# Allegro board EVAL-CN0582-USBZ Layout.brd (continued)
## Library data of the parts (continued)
J6 = CNBNC2P: User Part Number: UPN; Tolerance: N/A; alternate symbols: (); part number: CNBNC2P_TH-227161-1,E000900,CNAMP227161-1; tolerance: N/A
L1 = IND: User Part Number: UPN; Tolerance: 20; alternate symbols: (); part number: IND_SM-6.8UH,20,E017909,LSMSQ157H122; tolerance: 20
L2 L4 = IND: User Part Number: UPN; Tolerance: 20; alternate symbols: (); part number: IND_SM-4.7UH,20,E013623,LSMSQ157H122; tolerance: 20
L3 = IND: User Part Number: UPN; Tolerance: 20; alternate symbols: (); part number: IND_SM-8.2UH,20,E025126,LSMSQ157H161; tolerance: 20
M1 = MODUSB24P_4PSHLD: User Part Number: UPN; Tolerance: N/A; alternate symbols: (); part number: MODUSB24P_4PSHLD_SM-12401598E4#2A,E031205,M12401598E4_2A; tolerance: N/A
P1-P4 = CN2P: User Part Number: UPN; Tolerance: N/A; alternate symbols: (); part number: CN2P_TH-TSW-102-07-G-S,E031850,CNTHMHDR1X2L200W98H343; tolerance: N/A
P5 P14 = CN3P: User Part Number: UPN; Tolerance: N/A; alternate symbols: (); part number: CN3P_TH-1751251,E032001,CNPHOENIX1751251; tolerance: N/A
P7 = CN10P: User Part Number: UPN; Tolerance: N/A; alternate symbols: (); part number: CN10P_SM-TC2050-IDC,E021763,CNTC2050-IDC; tolerance: N/A
P8 = NC3P: Tolerance: N/A; User Part Number: UPN; alternate symbols: (); part number: NC3P_SM-TESTPAD3P,E020654,TP3SM29X147; tolerance: N/A
P9 P11 = CN10P: User Part Number: UPN; Tolerance: N/A; alternate symbols: (); part number: CN10P_TH-TSW-105-07-T-D,E054281,CNSAMTEC2X5H338LD36; tolerance: N/A
P10 = CN6P_ODD_EVEN: Tolerance: N/A; User Part Number: UPN; alternate symbols: (); part number: CN6P_ODD_EVEN_TH-TSW-103-08-T-D,E031364,CNSAMTEC2X3H330LD36; tolerance: N/A
P12 = CN2P: User Part Number: UPN; Tolerance: N/A; alternate symbols: (); part number: CN2P_TH-EDZ250/2,E013453,CNTH1X2H394; tolerance: N/A
Q1-Q4 Q9 Q10 = TRANNFET: User Part Number: UPN; Tolerance: N/A; alternate symbols: (); part number: TRANNFET_SM-DMN2005K-7,E011365,SOT23-2; tolerance: N/A
Q5-Q8 = TRANPMOSFET_V12: User Part Number: UPN; Tolerance: N/A; alternate symbols: (); part number: TRANPMOSFET_V12_SM-IRLML6401TRPBF,E023655,SOT23-M3; tolerance: N/A
R1 R6 R77 R79 R89 R98 R100 R101 R114 R149 R179 R184-R189 R191 R192 R196 R198-R200 R205-R207 R227 R229 R248 R257-R263 R287 R291 R292 R294 R296 R310 R313 R315-R317 R319 R320 R331 R332 R337 R338 R342 R352 R353 R355-R357 R368-R371 = RES: User Part Number: UPN; Tolerance: 1; alternate symbols: (R0402L,R0402L_ALT); part number: RES_SM-10K,E003751,1/10W,1,R0402; tolerance: 1
R2-R5 R111 R132 R139 R150 R154 R157 R181 R240-R244 R246 R277 R312 R314 R326 R327 R333 R349 R354 = RES: User Part Number: UPN; Tolerance: 1; alternate symbols: (R0402L,R0402L_ALT); part number: RES_SM-1K,E003763,1/10W,1,R0402; tolerance: 1
R7 R8 R13 R14 R23-R26 R47 R48 R57-R60 R78 R82-R88 R99 R102-R104 R109 R112 R113 R115-R117 R121 R128 R151 R153 R158 R180 R190 R195 R201-R204 R224 R225 R228 R230 R231 R234-R236 R239 R245 R247 R253 R255 R256 R264-R267 R274-R276 R278-R280 R283 R284 R293 R318 R323 R324 R330 R334 R335 R339 R340 R344 R350 R351 R358-R367 R372-R375 = RES: User Part Number: UPN; Tolerance: JUMPER; alternate symbols: (R0402L,R0402L_ALT); part number: RES_SM-0,E003438,1/10W,JUMPER,R0402; tolerance: JUMPER
R9 R10 R43 R44 R290 = RES: User Part Number: UPN; Tolerance: 1; alternate symbols: (R0402L); part number: RES_SM-120K,E015615,1/10W,1,R0402; tolerance: 1
R11 R12 R15 R16 R45 R46 R49 R50 R197 R208-R210 R297 R325 R328 R329 R347 = RES: User Part Number: UPN; Tolerance: 1; alternate symbols: (R0402L,R0402L_ALT); part number: RES_SM-100K,E003796,1/10W,1,R0402; tolerance: 1
R17 R18 R51 R52 = RES: User Part Number: UPN; Tolerance: 1; alternate symbols: (R0402L); part number: RES_SM-300,E049577,1/5W,1,R0402; tolerance: 1
R19 R20 R53 R54 R346 R348 = RES: User Part Number: UPN; Tolerance: 0.1; alternate symbols: (R0402L); part number: RES_SM-49.9K,E033966,1/16W,0.1,R0402; tolerance: 0.1
R21 R22 R55 R56 R108 = RES: User Part Number: UPN; Tolerance: 0.1; alternate symbols: (R0402L); part number: RES_SM-15K,E014275,1/16W,0.1,R0402; tolerance: 0.1
R27-R30 R61-R64 = RES: User Part Number: UPN; Tolerance: 0.1; alternate symbols: (R0402L); part number: RES_SM-750,E031657,1/16W,0.1,R0402; tolerance: 0.1
R31-R34 R65-R68 = RES: User Part Number: UPN; Tolerance: 0.1; alternate symbols: (R0402L); part number: RES_SM-374,E033965,1/10W,0.1,R0402; tolerance: 0.1
R35-R38 R69-R72 = RES: User Part Number: UPN; Tolerance: 0.1; alternate symbols: (R0402L); part number: RES_SM-2K,E031286,1/16W,0.1,R0402; tolerance: 0.1
R39-R42 R73-R76 = RES: User Part Number: UPN; Tolerance: 0.1; alternate symbols: (R0603L); part number: RES_SM-82.5,E018865,1/10W,0.1,R0603; tolerance: 0.1
R80 R106 = RES: User Part Number: UPN; Tolerance: 1; alternate symbols: (R0402L); part number: RES_SM-332K,E003766,1/10W,1,R0402; tolerance: 1
R81 = RES: User Part Number: UPN; Tolerance: 1; alternate symbols: (R0402L); part number: RES_SM-16K,E027681,1/10W,1,R0402; tolerance: 1
R90 = RES: User Part Number: UPN; Tolerance: 1; alternate symbols: (R0402L); part number: RES_SM-1MEG,E003749,1/10W,1,R0402; tolerance: 1
R91 = RES: User Part Number: UPN; Tolerance: 1; alternate symbols: (R0402L); part number: RES_SM-63.4K,E006803,1/10W,1,R0402; tolerance: 1
R92 = RES: User Part Number: UPN; Tolerance: 1; alternate symbols: (R0402L); part number: RES_SM-28K,E010020,1/10W,1,R0402; tolerance: 1
R93 = RES: User Part Number: UPN; Tolerance: 1; alternate symbols: (R0402L); part number: RES_SM-6.49K,E026140,1/10W,1,R0402; tolerance: 1
R94 = RES: User Part Number: UPN; Tolerance: 1; alternate symbols: (R0402L); part number: RES_SM-7.32K,E022433,1/10W,1,R0402; tolerance: 1
R95 = RES: User Part Number: UPN; Tolerance: 0.1; alternate symbols: (R0402L); part number: RES_SM-90.9K,E042560,1/16W,0.1,R0402; tolerance: 0.1
R96 = RES: User Part Number: UPN; Tolerance: 1; alternate symbols: (R0402L); part number: RES_SM-4.75K,E019642,1/16W,1,R0402; tolerance: 1
R97 = RES: User Part Number: UPN; Tolerance: 1; alternate symbols: (R0402L); part number: RES_SM-57.6K,E022063,1/16W,1,R0402; tolerance: 1
R105 = RES: User Part Number: UPN; Tolerance: 1; alternate symbols: (R0402L); part number: RES_SM-107K,E006341,1/10W,1,R0402; tolerance: 1
R107 = RES: User Part Number: UPN; Tolerance: 1; alternate symbols: (R0402L,R0402L_ALT); part number: RES_SM-47K,E008189,1/10W,1,R0402; tolerance: 1
R110 = RES: User Part Number: UPN; Tolerance: 1; alternate symbols: (R0402L); part number: RES_SM-243K,E024121,1/16W,1,R0402; tolerance: 1
R118-R120 R122-R127 R129 R130 R133 R134 R136 R137 R140 R141 R144-R147 R152 R161-R166 R168-R177 R212-R223 R232 R233 R268-R273 = RES: User Part Number: UPN; Tolerance: 1; alternate symbols: (R0402L); part number: RES_SM-22,E008191,1/10W,1,R0402; tolerance: 1
R131 R135 R182 = RES: User Part Number: UPN; Tolerance: 1; alternate symbols: (R0402L,R0402L_ALT); part number: RES_SM-3.3K,E010034,1/10W,1,R0402; tolerance: 1
R138 R142 R298-R301 = RES: User Part Number: UPN; Tolerance: 1; alternate symbols: (R0402L); part number: RES_SM-100,E016329,1/10W,1,R0402; tolerance: 1
R143 R193 R194 R211 R237 R238 R249 R321 R322 = RES: User Part Number: UPN; Tolerance: 1; alternate symbols: (R0402L,R0402L_ALT); part number: RES_SM-4.7K,E008190,1/10W,1,R0402; tolerance: 1
R148 = RES: User Part Number: UPN; Tolerance: 1; alternate symbols: (R0402L,R0402L_ALT); part number: RES_SM-2K,E003752,1/10W,1,R0402; tolerance: 1
R155 = RES: User Part Number: UPN; Tolerance: 1; alternate symbols: (R0402L); part number: RES_SM-249,E003759,1/16W,1,R0402; tolerance: 1
R156 = RES: User Part Number: UPN; Tolerance: 1; alternate symbols: (R0402L); part number: RES_SM-102K,E020517,1/10W,1,R0402; tolerance: 1
R159 R160 = RES: User Part Number: UPN; Tolerance: 1; alternate symbols: (R0603L); part number: RES_SM-3.4K,E026189,1/10W,1,R0603; tolerance: 1
R167 = RES: User Part Number: UPN; Tolerance: 1; alternate symbols: (R0402L); part number: RES_SM-200,E003753,1/10W,1,R0402; tolerance: 1
R178 = RES: User Part Number: UPN; Tolerance: 1; alternate symbols: (R0402L); part number: RES_SM-6.04K,E004030,1/10W,1,R0402; tolerance: 1
R183 = RES: User Part Number: UPN; Tolerance: 0.5; alternate symbols: (R0402L); part number: RES_SM-33,E012477,1/16W,0.5,R0402; tolerance: 0.5
R226 = RES: User Part Number: UPN; Tolerance: 0.1; alternate symbols: (R0603L); part number: RES_SM-5.1K,E003967,1/10W,0.1,R0603; tolerance: 0.1
R250 R251 = RES: User Part Number: UPN; Tolerance: 1; alternate symbols: (R0402L); part number: RES_SM-619,E006549,1/10W,1,R0402; tolerance: 1
R252 = RES: User Part Number: UPN; Tolerance: 5; alternate symbols: (R0402L); part number: RES_SM-120,E003453,1/10W,5,R0402; tolerance: 5
R254 R311 R345 = RES: User Part Number: UPN; Tolerance: 1; alternate symbols: (R0402L); part number: RES_SM-10.5K,E007860,1/10W,1,R0402; tolerance: 1
R281 R282 R285 R286 = RES: User Part Number: UPN; Tolerance: 1; alternate symbols: (R0402L); part number: RES_SM-499K,E019889,1/10W,1,R0402; tolerance: 1
R288 = RES: User Part Number: UPN; Tolerance: 1; alternate symbols: (R0402L); part number: RES_SM-33K,E021200,1/16W,1,R0402; tolerance: 1
R289 = RES: User Part Number: UPN; Tolerance: 1; alternate symbols: (R0402L); part number: RES_SM-845K,E033878,1/16W,1,R0402; tolerance: 1
R295 = RES: User Part Number: UPN; Tolerance: 1; alternate symbols: (R0402L); part number: RES_SM-42.2K,E020077,1/10W,1,R0402; tolerance: 1
R302-R309 = RES: User Part Number: UPN; Tolerance: 1; alternate symbols: (R0402L); part number: RES_SM-17.4K,E014042,1/16W,1,R0402; tolerance: 1
R336 = RES: User Part Number: UPN; alternate symbols: (R0402L); part number: RES_SM-1,E020530,1/6W,1,R0402
R341 = RES: User Part Number: UPN; Tolerance: 1; alternate symbols: (R1206L); part number: RES_SM-249,E003192,1/4W,1,R1206; tolerance: 1
R343 = RES: User Part Number: UPN; Tolerance: 1; alternate symbols: (R0402L,R0402L_ALT); part number: RES_SM-7.5K,E023755,1/10W,1,R0402; tolerance: 1
S1 = SWSPST4P_V6: Tolerance: N/A; User Part Number: UPN; alternate symbols: (); part number: SWSPST4P_V6_SM-219-2LPSTR,E029047,SWSML258W264H180; tolerance: N/A
S2 = SWSPST2PIN_V3: User Part Number: UPN; Tolerance: N/A; alternate symbols: (); part number: SWSPST2PIN_V3_TH-PTS645VL31-2 LFS,E031124,SWTHRAL295W287H244; tolerance: N/A
TP13 TP36-TP38 TP45-TP55 TP62 TP63 TP70 = NCTESTPAD: Tolerance: N/A; User Part Number: UPN; alternate symbols: (); part number: NCTESTPAD_SM-TESTPAD,E019801,TPSMC40; tolerance: N/A
U1 = ICCYUSB301X: User Part Number: UPN; Tolerance: N/A; alternate symbols: (); part number: ICCYUSB301X_SM-CYUSB3014-BZXI,E042775,BGA121_A; tolerance: N/A
U2 = ICW25Q64JV: Tolerance: N/A; User Part Number: UPN; alternate symbols: (); part number: ICW25Q64JV_SM-W25Q64JVSSIM,E057294,SO8_A; tolerance: N/A
U3 U33 U38 U41 = 74LVC1G04: User Part Number: UPN; Tolerance: N/A; alternate symbols: (); part number: 74LVC1G04_SM-SN74AUP1G17DBVR,E038106,SOT23-5L; tolerance: N/A
U4 U5 U7 U8 = LINLT3092: User Part Number: UPN; Tolerance: N/A; alternate symbols: (); part number: LINLT3092_SM-LT3092ETS8#TRMPBF,E030126,TSOT-8; tolerance: N/A
U6 U9 U10 U21 = ADA4945_1: User Part Number: UPN; Tolerance: N/A; alternate symbols: (); part number: ADA4945_1_SM-ADA4945-1ACPZ-R7,E028779,QFN16_3X3_PAD1_6X1_6; tolerance: N/A
U11 = ADP7142: User Part Number: UPN; Tolerance: N/A; alternate symbols: (); part number: ADP7142_SM-ADP7142ACPZN-R7,E017499,DFN6_2X2_PAD1_6X1; tolerance: N/A
U12 = ADLTC4332: User Part Number: UPN; Tolerance: N/A; alternate symbols: (); part number: ADLTC4332_SM-LTC4332HUFD#PBF,E033269,QFN20_5X4_PAD3_65X2_65; tolerance: N/A
U13 = ADLT8330: User Part Number: UPN; Tolerance: N/A; alternate symbols: (); part number: ADLT8330_SM-LT8330EDDB#TRMPBF,E056322,DFN8_3X2_PAD2_15X0_56; tolerance: N/A
U14 U26 = ADP1708: User Part Number: UPN; Tolerance: N/A; alternate symbols: (); part number: ADP1708_SM-ADP1708ACPZ,E011629,QFN8_3X3_PAD1_75X1_45-1; tolerance: N/A
U15 = ADP5071_V2: Tolerance: N/A; User Part Number: UPN; alternate symbols: (); part number: ADP5071_V2_SM-ADP5071AREZ,E028605,TSSOP20_PAD4_2X3; tolerance: N/A
U16 = AD568XR_V5: User Part Number: UPN; Tolerance: N/A; alternate symbols: (); part number: AD568XR_V5_SM-AD5686RBCPZ-RL7,E012503,QFN16_3X3_PAD1_6X1_6; tolerance: N/A
U17 = ADR45XX: Tolerance: N/A; User Part Number: UPN; alternate symbols: (); part number: ADR45XX_SM-ADR4540BRZ,E017544,SO8; tolerance: N/A
U18 = AD7768_4: Tolerance: N/A; User Part Number: UPN; alternate symbols: (); part number: AD7768_4_SM-AD7768-4BSTZ,E026619,LQFP64; tolerance: N/A
U19 = AD9833: Tolerance: N/A; User Part Number: UPN; alternate symbols: (); part number: AD9833_SM-AD9833BRMZ,E048164,RM10; tolerance: N/A
U20 = AD55X3: Tolerance: N/A; User Part Number: UPN; alternate symbols: (); part number: AD55X3_SM-AD5543CRMZ,E019088,MSOP8; tolerance: N/A
U22 U27-U29 = ADG5436: Tolerance: N/A; User Part Number: UPN; alternate symbols: (); part number: ADG5436_SM-ADG5436BCPZ,E041004,QFN16_4X4_PAD2_6X2_6; tolerance: N/A
U23 U31 = ADP7118_V2: User Part Number: UPN; Tolerance: N/A; alternate symbols: (); part number: ADP7118_V2_SM-ADP7118AUJZ-5.0,E022999,TSOT-5; tolerance: N/A
U24 = ADP7182_V5: User Part Number: UPN; Tolerance: N/A; alternate symbols: (); part number: ADP7182_V5_SM-ADP7182ACPZN,E024308,DFN6_2X2_PAD1_6X1; tolerance: N/A
U25 U34 U43 U44 = ADG5401: Tolerance: N/A; User Part Number: UPN; alternate symbols: (); part number: ADG5401_SM-ADG5401BRMZ,E032461,MSOP8; tolerance: N/A
U30 = ADLTC3112: Tolerance: N/A; User Part Number: UPN; alternate symbols: (); part number: ADLTC3112_SM-LTC3112IFE#PBF,E055419,TSSOP20_PAD4_95X2_74; tolerance: N/A
U32 = ADG1219: User Part Number: UPN; Tolerance: N/A; alternate symbols: (); part number: ADG1219_SM-ADG1219BRJZ,E014765,SOT23_8; tolerance: N/A
U35 = ICCBTU02043: User Part Number: UPN; Tolerance: N/A; alternate symbols: (); part number: ICCBTU02043_SM-CBTU02043HEJ,E031290,HUQFN16; tolerance: N/A
U36 = ICPTN5150A: User Part Number: UPN; Tolerance: N/A; alternate symbols: (); part number: ICPTN5150A_SM-PTN5150AHXMP,E031253,XFQFN12; tolerance: N/A
U37 = ADG839: Tolerance: N/A; User Part Number: UPN; alternate symbols: (); part number: ADG839_SM-ADG839YKSZ-500RL7,E008077,SC70-6; tolerance: N/A
U39 = ICMAX14595: User Part Number: UPN; Tolerance: N/A; alternate symbols: (); part number: ICMAX14595_SM-MAX14595ETA+T,E033250,DFN8_2X2; tolerance: N/A
U40 = ICMAX7312: Tolerance: N/A; User Part Number: UPN; alternate symbols: (); part number: ICMAX7312_SM-MAX7312AAG+,E028084,SSOP24-2; tolerance: N/A
U42 = 74125_V5: User Part Number: UPN; Tolerance: N/A; alternate symbols: (); part number: 74125_V5_SM-74AUP1G125GW,125,E024311,SOT353; tolerance: N/A
Y1 = XTAL4PIN_V3: Tolerance: 10; User Part Number: UPN; alternate symbols: (); part number: XTAL4PIN_V3_SM-19.2MEGHZ,E031704,YSML79W63H20; tolerance: 10
Y2 = XTALOSC4P_V6: Tolerance: N/A; User Part Number: UPN; alternate symbols: (); part number: XTALOSC4P_V6_SM-32.768KHZ,E025311,YSML98W79H35; tolerance: N/A
Y3 Y4 = XTALOSC4P_V6: Tolerance: N/A; User Part Number: UPN; alternate symbols: (); part number: XTALOSC4P_V6_SM-25MEGHZ,E027336,YSML197W126H51; tolerance: N/A
Y5 = XTALOSC4P_V43: Tolerance: N/A; User Part Number: UPN; alternate symbols: (); part number: XTALOSC4P_V43_SM-32.768MEGHZ,E057106,YSML98W79H35; tolerance: N/A
Y6 = XTALOSC4P_V2: Tolerance: N/A; User Part Number: UPN; alternate symbols: (); part number: XTALOSC4P_V2_SM-10MEGHZ,E012665,XSM4PL275W200H55; tolerance: N/A

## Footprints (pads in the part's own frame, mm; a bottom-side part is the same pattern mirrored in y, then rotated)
BGA121_A
  round 0.254 smd: A1(-4,-4) A2(-4,-3.2) A3(-4,-2.4) A4(-4,-1.6) A5(-4,-0.8) A6(-4,0) A7(-4,0.8) A8(-4,1.6) A9(-4,2.4) A10(-4,3.2) A11(-4,4) B1(-3.2,-4) B2(-3.2,-3.2) B3(-3.2,-2.4) B4(-3.2,-1.6) B5(-3.2,-0.8) B6(-3.2,0) B7(-3.2,0.8) B8(-3.2,1.6) B9(-3.2,2.4) B10(-3.2,3.2) B11(-3.2,4) C1(-2.4,-4) C2(-2.4,-3.2) C3(-2.4,-2.4) C4(-2.4,-1.6) C5(-2.4,-0.8) C6(-2.4,0) C7(-2.4,0.8) C8(-2.4,1.6) C9(-2.4,2.4) C10(-2.4,3.2) C11(-2.4,4) D1(-1.6,-4) D2(-1.6,-3.2) D3(-1.6,-2.4) D4(-1.6,-1.6) D5(-1.6,-0.8) D6(-1.6,0) D7(-1.6,0.8) D8(-1.6,1.6) D9(-1.6,2.4) D10(-1.6,3.2) D11(-1.6,4) E1(-0.8,-4) E2(-0.8,-3.2) E3(-0.8,-2.4) E4(-0.8,-1.6) E5(-0.8,-0.8) E6(-0.8,0) E7(-0.8,0.8) E8(-0.8,1.6) E9(-0.8,2.4) E10(-0.8,3.2) E11(-0.8,4) F1(0,-4) F2(0,-3.2) F3(0,-2.4) F4(0,-1.6) F5(0,-0.8) F6(0,0) F7(0,0.8) F8(0,1.6) F9(0,2.4) F10(0,3.2) F11(0,4) G1(0.8,-4) G2(0.8,-3.2) G3(0.8,-2.4) G4(0.8,-1.6) G5(0.8,-0.8) G6(0.8,0) G7(0.8,0.8) G8(0.8,1.6) G9(0.8,2.4) G10(0.8,3.2) G11(0.8,4) H1(1.6,-4) H2(1.6,-3.2) H3(1.6,-2.4) H4(1.6,-1.6) H5(1.6,-0.8) H6(1.6,0) H7(1.6,0.8) H8(1.6,1.6) H9(1.6,2.4) H10(1.6,3.2) H11(1.6,4) J1(2.4,-4) J2(2.4,-3.2) J3(2.4,-2.4) J4(2.4,-1.6) J5(2.4,-0.8) J6(2.4,0) J7(2.4,0.8) J8(2.4,1.6) J9(2.4,2.4) J10(2.4,3.2) J11(2.4,4) K1(3.2,-4) K2(3.2,-3.2) K3(3.2,-2.4) K4(3.2,-1.6) K5(3.2,-0.8) K6(3.2,0) K7(3.2,0.8) K8(3.2,1.6) K9(3.2,2.4) K10(3.2,3.2) K11(3.2,4) L1(4,-4) L2(4,-3.2) L3(4,-2.4) L4(4,-1.6) L5(4,-0.8) L6(4,0) L7(4,0.8) L8(4,1.6) L9(4,2.4) L10(4,3.2) L11(4,4)
C0402
  rect 0.584x0.66 smd: 1(-0.5,0) 2(0.5,0)
C0603
  rect 0.94x0.991 smd: 1(-0.8,0) 2(0.8,0)
C0805H60
  rect 1.295x1.6 smd: 1(-0.953,0) 2(0.953,0)
C1210-2
  rect 1.575x2.692 smd: 1(-1.397,0) 2(1.397,0)
C7343
  rect 2.591x2.413 smd: N(3.2,0) P(-3.2,0)
CNAMP227161-1
  round 2.54 hole 2.032: (5.08,5.08) (5.08,-5.08)
  round 1.397 hole 0.889: 1(0,0) 2(0,2.54)
CNPHOENIX1751251
  rect 1.778x1.778 hole 1.27: 1(0,0)
  round 1.778 hole 1.27: 2(3.5,0) 3(7,0)
CNSAMTEC2X3H330LD36
  rect 1.651x1.651 hole 1.143: 1(0,0)
  round 1.651 hole 1.143: 2(0,2.54) 3(2.54,0) 4(2.54,2.54) 5(5.08,0) 6(5.08,2.54)
CNSAMTEC2X5H338LD36
  rect 1.651x1.651 hole 1.143: 1(0,0)
  round 1.651 hole 1.143: 2(0,2.54) 3(2.54,0) 4(2.54,2.54) 5(5.08,0) 6(5.08,2.54) 7(7.62,0) 8(7.62,2.54) 9(10.16,0) 10(10.16,2.54)
CNSMARAL594W276H393
  round 2.159 hole 1.651: 1(0,0) 2(-2.54,2.54) 3(2.54,2.54) 4(-2.54,-2.54) 5(2.54,-2.54)
CNTC2050-IDC
  round 2.896 hole 2.388 unplated: (-3.81,2.54) (-3.81,-2.54) (1.905,2.54) (1.905,-2.54)
  round 1.143 hole 0.991 unplated: (-3.81,0) (3.81,1.016) (3.81,-1.016)
  round 0.787 smd: 1(-2.54,-0.635) 2(-1.27,-0.635) 3(0,-0.635) 4(1.27,-0.635) 5(2.54,-0.635) 6(2.54,0.635) 7(1.27,0.635) 8(0,0.635) 9(-1.27,0.635) 10(-2.54,0.635)
CNTH1X2H394
  rect 1.778x1.778 hole 1.27: 1(0,0)
  round 1.778 hole 1.27: 2(5.08,0)
CNTHMHDR1X2L200W98H343
  rect 1.651x1.651 hole 1.143: 1(0,0)
  round 1.651 hole 1.143: 2(2.54,0)
DFN2_1X0_6_NP_A
  rect 0.406x0.711 smd: 1(-0.35,0) 2(0.35,0)
DFN6_2X2_PAD1_6X1
  oval 0.305x0.864 smd: 1(-0.65,-1.082) 2(0,-1.082) 3(0.65,-1.082) 4(0.65,1.082) 5(0,1.082) 6(-0.65,1.082)
  rect 1.6x0.991 smd: PAD(0,0)
DFN8_2X2
  oval 0.254x1.041 smd: 1(-0.75,-0.85) 2(-0.25,-0.85) 3(0.25,-0.85) 4(0.75,-0.85) 5(0.75,0.85) 6(0.25,0.85) 7(-0.25,0.85) 8(-0.75,0.85)
DFN8_3X2_PAD2_15X0_56
  oval 0.305x0.838 smd: 1(-0.75,-0.95) 2(-0.25,-0.95) 3(0.25,-0.95) 4(0.75,-0.95) 5(0.75,0.95) 6(0.25,0.95) 7(-0.25,0.95) 8(-0.75,0.95)
  rect 2.159x0.61 smd: PAD(0,0)
DO214AC_C
  rect 1.397x1.651 smd: 1(-2.013,0) 2(2.013,0)
F1206H46
  rect 1.448x1.803 smd: 1(-1.473,0) 2(1.473,0)
HUQFN16
  rect 0.254x0.457 smd: 1(-1,-0.704) 2(-0.6,-0.704) 3(-0.2,-0.704) 4(0.2,-0.704) 5(0.6,-0.704) 6(1,-0.704) 9(1,0.704) 10(0.6,0.704) 11(0.2,0.704) 12(-0.2,0.704) 13(-0.6,0.704) 14(-1,0.704)
  rect 0.457x0.254 smd: 7(1.104,-0.2) 8(1.104,0.2) 15(-1.104,0.2) 16(-1.104,-0.2)
  rect 1.397x0.61 smd: PAD(0,0)
L0603
  rect 0.94x0.991 smd: 1(-0.8,0) 2(0.8,0)
L0805
  rect 1.194x1.448 smd: 1(-0.85,0) 2(0.85,0)
LED0402
  rect 0.508x0.61 smd: A(0.454,0) C(-0.454,0)
LQFP64
  rect 0.254x1.651 smd: 1(-3.75,-5.675) 2(-3.25,-5.675) 3(-2.75,-5.675) 4(-2.25,-5.675) 5(-1.75,-5.675) 6(-1.25,-5.675) 7(-0.75,-5.675) 8(-0.25,-5.675) 9(0.25,-5.675) 10(0.75,-5.675) 11(1.25,-5.675) 12(1.75,-5.675) 13(2.25,-5.675) 14(2.75,-5.675) 15(3.25,-5.675) 16(3.75,-5.675) 33(3.75,5.675) 34(3.25,5.675) 35(2.75,5.675) 36(2.25,5.675) 37(1.75,5.675) 38(1.25,5.675) 39(0.75,5.675) 40(0.25,5.675) 41(-0.25,5.675) 42(-0.75,5.675) 43(-1.25,5.675) 44(-1.75,5.675) 45(-2.25,5.675) 46(-2.75,5.675) 47(-3.25,5.675) 48(-3.75,5.675)
  rect 1.651x0.254 smd: 17(5.675,-3.75) 18(5.675,-3.25) 19(5.675,-2.75) 20(5.675,-2.25) 21(5.675,-1.75) 22(5.675,-1.25) 23(5.675,-0.75) 24(5.675,-0.25) 25(5.675,0.25) 26(5.675,0.75) 27(5.675,1.25) 28(5.675,1.75) 29(5.675,2.25) 30(5.675,2.75) 31(5.675,3.25) 32(5.675,3.75) 49(-5.675,3.75) 50(-5.675,3.25) 51(-5.675,2.75) 52(-5.675,2.25) 53(-5.675,1.75) 54(-5.675,1.25) 55(-5.675,0.75) 56(-5.675,0.25) 57(-5.675,-0.25) 58(-5.675,-0.75) 59(-5.675,-1.25) 60(-5.675,-1.75) 61(-5.675,-2.25) 62(-5.675,-2.75) 63(-5.675,-3.25) 64(-5.675,-3.75)
LSMSQ157H122
  rect 0.965x3.708 smd: 1(-1.181,0) 2(1.181,0)
LSMSQ157H161
  rect 0.965x3.708 smd: 1(-1.181,0) 2(1.181,0)
M12401598E4_2A
  round 0.787 hole 0.66 unplated: (-3.6,4.34)
  oval 1.067x0.787 hole 0.94x0.66 unplated: (3.6,4.34)
  rect 0.305x0.711 smd: A1(-2.75,5) A2(-2.25,5) A3(-1.75,5) A4(-1.25,5) A5(-0.75,5) A6(-0.25,5) A7(0.25,5) A8(0.75,5) A9(1.25,5) A10(1.75,5) A11(2.25,5) A12(2.75,5) B1(2.5,3.3) B2(2,3.3) B3(1.5,3.3) B4(1,3.3) B5(0.5,3.3) B6(0,3.3) B7(-0.5,3.3) B8(-1,3.3) B9(-1.5,3.3) B10(-2,3.3) B11(-2.5,3.3) B12(-3,3.3)
  oval 0.813x1.397 hole 0.508x1.118: SH1(-4.13,3.09) SH2(4.13,3.09) SH3(-4.49,-2.86) SH4(4.49,-2.86)
MSOP8
  rect 0.305x1.321 smd: 1(-0.975,-2.3) 2(-0.325,-2.3) 3(0.325,-2.3) 4(0.975,-2.3) 5(0.975,2.3) 6(0.325,2.3) 7(-0.325,2.3) 8(-0.975,2.3)
QFN8_3X3_PAD1_75X1_45-1
  oval 0.305x0.711 smd: 1(-0.75,-1.371) 2(-0.25,-1.371) 3(0.25,-1.371) 4(0.75,-1.371) 5(0.75,1.371) 6(0.25,1.371) 7(-0.25,1.371) 8(-0.75,1.371)
  rect 1.854x1.524 smd: PAD(0,0)
QFN16_3X3_PAD1_6X1_6
  oval 0.305x0.889 smd: 1(-0.75,-1.5) 2(-0.25,-1.5) 3(0.25,-1.5) 4(0.75,-1.5) 9(0.75,1.5) 10(0.25,1.5) 11(-0.25,1.5) 12(-0.75,1.5)
  oval 0.889x0.305 smd: 5(1.5,-0.75) 6(1.5,-0.25) 7(1.5,0.25) 8(1.5,0.75) 13(-1.5,0.75) 14(-1.5,0.25) 15(-1.5,-0.25) 16(-1.5,-0.75)
  rect 1.6x1.6 smd: PAD(0,0)
QFN16_4X4_PAD2_6X2_6
  oval 0.356x0.838 smd: 1(-0.975,-1.95) 2(-0.325,-1.95) 3(0.325,-1.95) 4(0.975,-1.95) 9(0.975,1.95) 10(0.325,1.95) 11(-0.325,1.95) 12(-0.975,1.95)
  oval 0.838x0.356 smd: 5(1.95,-0.975) 6(1.95,-0.325) 7(1.95,0.325) 8(1.95,0.975) 13(-1.95,0.975) 14(-1.95,0.325) 15(-1.95,-0.325) 16(-1.95,-0.975)
  rect 2.591x2.591 smd: PAD(0,0)
QFN20_5X4_PAD3_65X2_65
  oval 0.279x0.737 smd: 1(-1.25,-1.893) 2(-0.75,-1.893) 3(-0.25,-1.893) 4(0.25,-1.893) 5(0.75,-1.893) 6(1.25,-1.893) 11(1.25,1.893) 12(0.75,1.893) 13(0.25,1.893) 14(-0.25,1.893) 15(-0.75,1.893) 16(-1.25,1.893)
  oval 0.737x0.279 smd: 7(2.393,-0.75) 8(2.393,-0.25) 9(2.393,0.25) 10(2.393,0.75) 17(-2.393,0.75) 18(-2.393,0.25) 19(-2.393,-0.25) 20(-2.393,-0.75)
  rect 3.658x2.642 smd: PAD(0,0)
R0402
  rect 0.635x0.737 smd: 1(-0.5,0) 2(0.5,0)
R0603
  rect 0.787x0.991 smd: 1(-0.85,0) 2(0.85,0)
R1206
  rect 1.041x1.753 smd: 1(-1.5,0) 2(1.5,0)
RM10
  rect 0.305x1.321 smd: 1(-1,-2.171) 2(-0.5,-2.171) 3(0,-2.171) 4(0.5,-2.171) 5(1,-2.171) 6(1,2.171) 7(0.5,2.171) 8(0,2.171) 9(-0.5,2.171) 10(-1,2.171)
SC70-6
  rect 0.406x0.508 smd: 1(-0.65,-0.95) 2(0,-0.95) 3(0.65,-0.95) 4(0.65,0.95) 5(0,0.95) 6(-0.65,0.95)
SO8
  rect 0.61x2.184 smd: 1(-1.905,-2.54) 2(-0.635,-2.54) 3(0.635,-2.54) 4(1.905,-2.54) 5(1.905,2.54) 6(0.635,2.54) 7(-0.635,2.54) 8(-1.905,2.54)
SO8_A
  rect 0.61x1.6 smd: 1(-1.905,-3.6) 2(-0.635,-3.6) 3(0.635,-3.6) 4(1.905,-3.6) 5(1.905,3.6) 6(0.635,3.6) 7(-0.635,3.6) 8(-1.905,3.6)
SOD123FL
  rect 0.914x1.219 smd: A(1.638,0) C(-1.638,0)
SOD128
  rect 0.991x1.93 smd: A(2.21,0) C(-2.21,0)
SOD323
  rect 1.27x0.889 smd: A(1.143,0) C(-1.143,0)
SOD323-3
  rect 0.94x0.813 smd: A(1.27,0) C(-1.27,0)
SOT23-2
  rect 0.889x1.397 smd: D(0,1) G(-0.958,-1) S(0.958,-1)
SOT23-5L
  rect 0.508x1.524 smd: 1(-0.95,-1.17) 2(0,-1.17) 3(0.95,-1.17) 4(0.95,1.17) 5(-0.95,1.17)
SOT23-M3
  rect 0.787x0.889 smd: 1(-0.94,-1.003) 2(0.94,-1.003) 3(0,1.003)
SOT23_6-2
  rect 0.711x0.991 smd: 1(-0.95,-1.2) 2(0,-1.2) 3(0.95,-1.2) 4(0.95,1.2) 5(0,1.2) 6(-0.95,1.2)
SOT23_8
  rect 0.381x1.372 smd: 1(-0.975,-1.22) 2(-0.325,-1.22) 3(0.325,-1.22) 4(0.975,-1.22) 5(0.975,1.22) 6(0.325,1.22) 7(-0.325,1.22) 8(-0.975,1.22)
SOT353
  rect 0.33x0.94 smd: 1(-0.65,-0.89) 2(0,-0.89) 3(0.65,-0.89) 4(0.65,0.89) 5(-0.65,0.89)
SOT1215
  rect 0.356x0.406 smd: 1(-0.375,-0.453) 2(0.375,-0.453) 3(0,0.453)
  rect 0.914x0.203 smd: 4(0,0)
SSOP24-2
  rect 0.33x1.778 smd: 1(-3.575,-3.505) 2(-2.925,-3.505) 3(-2.275,-3.505) 4(-1.625,-3.505) 5(-0.975,-3.505) 6(-0.325,-3.505) 7(0.325,-3.505) 8(0.975,-3.505) 9(1.625,-3.505) 10(2.275,-3.505) 11(2.925,-3.505) 12(3.575,-3.505) 13(3.575,3.505) 14(2.925,3.505) 15(2.275,3.505) 16(1.625,3.505) 17(0.975,3.505) 18(0.325,3.505) 19(-0.325,3.505) 20(-0.975,3.505) 21(-1.625,3.505) 22(-2.275,3.505) 23(-2.925,3.505) 24(-3.575,3.505)
SWSML258W264H180
  rect 1.118x2.438 smd: 1A(-1.27,-4.3) 1B(-1.27,4.3) 2A(1.27,-4.3) 2B(1.27,4.3)
SWTHRAL295W287H244
  round 1.676 hole 1.295 unplated: (-1.25,2.55) (5.75,2.55)
  rect 1.524x1.524 hole 1.016: 1(0,0)
  round 1.524 hole 1.016: 2(4.5,0)
TP3SM29X147
  rect 0.737x3.734 smd: 1(-1.27,-1.13) 2(0,1.13) 3(1.27,-1.13)
TPSMC30
  round 0.762 smd: 1(0,0)
TPSMC40
  round 1.016 smd: 1(0,0)
TSOT23_6
  rect 0.61x1.219 smd: 1(-0.95,-1.31) 2(0,-1.31) 3(0.95,-1.31) 4(0.95,1.31) 5(0,1.31) 6(-0.95,1.31)
TSOT-5
  rect 0.508x1.524 smd: 1(-0.95,-1.17) 2(0,-1.17) 3(0.95,-1.17) 4(0.95,1.17) 5(-0.95,1.17)
TSOT-8
  rect 0.406x1.067 smd: 1(-0.975,-1.3) 2(-0.325,-1.3) 3(0.325,-1.3) 4(0.975,-1.3) 5(0.975,1.3) 6(0.325,1.3) 7(-0.325,1.3) 8(-0.975,1.3)
TSSOP20_PAD4_2X3
  rect 0.432x1.778 smd: 1(-2.925,-2.97) 2(-2.275,-2.97) 3(-1.625,-2.97) 4(-0.975,-2.97) 5(-0.325,-2.97) 6(0.325,-2.97) 7(0.975,-2.97) 8(1.625,-2.97) 9(2.275,-2.97) 10(2.925,-2.97) 11(2.925,2.97) 12(2.275,2.97) 13(1.625,2.97) 14(0.975,2.97) 15(0.325,2.97) 16(-0.325,2.97) 17(-0.975,2.97) 18(-1.625,2.97) 19(-2.275,2.97) 20(-2.925,2.97)
  rect 4.191x2.997 smd: PAD(0,0)
TSSOP20_PAD4_95X2_74
  rect 0.381x1.27 smd: 1(-2.925,-2.81) 2(-2.275,-2.81) 3(-1.625,-2.81) 4(-0.975,-2.81) 5(-0.325,-2.81) 6(0.325,-2.81) 7(0.975,-2.81) 8(1.625,-2.81) 9(2.275,-2.81) 10(2.925,-2.81) 11(2.925,2.81) 12(2.275,2.81) 13(1.625,2.81) 14(0.975,2.81) 15(0.325,2.81) 16(-0.325,2.81) 17(-0.975,2.81) 18(-1.625,2.81) 19(-2.275,2.81) 20(-2.925,2.81)
  rect 4.953x2.743 smd: PAD(0,0)
unnamed
  round 1.016 smd: (0,0)
WLCSP15H22
  round 0.203 smd: A1(-0.4,-1) A2(-0.4,-0.6) A3(-0.4,-0.2) A4(-0.4,0.2) A5(-0.4,0.6) A6(-0.4,1) B1(0,-0.8) B2(0,0) B3(0,0.8) C1(0.4,-1) C2(0.4,-0.6) C3(0.4,-0.2) C4(0.4,0.2) C5(0.4,0.6) C6(0.4,1)
XFQFN12
  rect 0.229x0.711 smd: 1(-0.2,-0.594) 2(0.2,-0.594) 7(0.2,0.594) 8(-0.2,0.594)
  rect 0.457x0.229 smd: 3(0.721,-0.6) 4(0.721,-0.2) 5(0.721,0.2) 6(0.721,0.6) 9(-0.721,0.6) 10(-0.721,0.2) 11(-0.721,-0.2) 12(-0.721,-0.6)
XSM4PL275W200H55
  rect 1.803x2.007 smd: 1(-2.54,-2) 2(2.54,-2) 3(2.54,2) 4(-2.54,2)
YSML79W63H20
  rect 0.94x0.838 smd: 1(-0.725,-0.575) 2(0.725,-0.575) 3(0.725,0.575) 4(-0.725,0.575)
YSML98W79H35
  rect 1.092x0.991 smd: 1(-0.921,-0.72) 2(0.921,-0.72) 3(0.921,0.72) 4(-0.921,0.72)
YSML197W126H51
  rect 1.397x1.194 smd: 1(-1.27,-1.1) 2(1.27,-1.1) 3(1.27,1.1) 4(-1.27,1.1)

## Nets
5V_SUPPLY: A1.6 A2.6 A3.6 A4.6 A6.6 A9.6 A10.8 A11.8 A12.8 A13.8 A15.6 A16.6 A17.6 A18.6 A19.6 C35.1 C36.1 C37.1 C38.1 C47.1 C48.1 C49.1 C50.1 C67.1 C68.1 C69.1 C70.1 C79.1 C80.1 C81.1 C82.1 C102.1 C105.2(N2) C132.1 C133.1 C134.1 C137.1 C158.1 C159.1 C160.1 C177.1 C178.2(N2) C179.2(N2) C184.1 C191.1 C192.2(N2) C207.1 C210.1 C229.1 C230.1 C233.1 C282.1 C283.1 C299.1 C300.1 C301.1 C302.1 C303.1 C304.1 C305.1 C306.1 DS2.A(P) E2.1 P8.1 R8.2(N2) R293.1 R304.2(N2) R305.2(N2) R308.2(N2) R309.2(N2) R319.2(N2) R321.1 R322.1 R324.2(N2) U1.E11 U6.6 U6.7 U6.8 U9.6 U9.7 U9.8 U10.6 U10.7 U10.8 U16.3 U17.2 U19.2 U20.7 U21.6 U21.7 U21.8 U39.8 U40.24(V+)
5V_USB: C2.2(N2) C3.2(N2) C241.1 C242.2(N2) C278.2(N2) E5.2(N2) Q5.3 R101.2(N2) R297.1 TP45.1(N1)
26V8_SUPPLY: C106.2(N2) C108.2(N2) C311.1 D1.C E12.1 R90.2(N2) TP47.1(N1)
26V_SUPPLY: C25.1 C26.1 C29.1 C30.1 C57.1 C58.1 C61.1 C62.1 C95.2(N2) C96.1 C107.1 C114.1 C115.2(N2) C118.2(N2) C121.1 C127.1 C129.2(N2) C130.2(N2) C211.1 C212.1 C249.1 C250.1 C295.1 C296.1 C297.1 C298.1 R80.2(N2) TP46.1(N1) U4.7 U4.8 U5.7 U5.8 U7.7 U7.8 U8.7 U8.8 U11.1(VOUT) U22.11 U25.4 U27.11 U28.11 U29.11 U34.4 U43.4 U44.4
AVDD: C196.1 C199.1 E9.1 U1.A7
DGND: A1.2 A1.5 A2.2 A2.5 A3.2 A3.5 A4.2 A4.5 A6.2 A8.3 A9.2 A10.4(V-) A11.4(V-) A12.4(V-) A13.4(V-) A15.2 A16.2 A16.5 A17.2 A17.5 A18.2 A18.5 A19.2 A19.5 C1.2(N2) C2.1 C3.1 C4.1 C5.1 C6.1 C7.1 C8.1 C9.1 C10.1 C11.1 C12.2(N2) C13.2(N2) C14.2(N2) C15.1 C16.1 C17.2(N2) C18.1 C19.2(N2) C20.1 C21.1 C22.2(N2) C23.1 C24.2(N2) C25.2(N2) C26.2(N2) C31.2(N2) C32.2(N2) C35.2(N2) C36.2(N2) C37.2(N2) C38.2(N2) C47.2(N2) C48.2(N2) C49.2(N2) C50.2(N2) C53.1 C54.2(N2) C55.1 C56.1 C57.2(N2) C58.2(N2) C63.2(N2) C64.2(N2) C67.2(N2) C68.2(N2) C69.2(N2) C70.2(N2) C79.2(N2) C80.2(N2) C81.2(N2) C82.2(N2) C85.1 C86.1 C87.1 C88.1 C89.2(N2) C90.2(N2) C91.2(N2) C92.1 C93.2(N2) C94.2(N2) C96.2(N2) C97.2(N2) C98.1 C99.2(N2) C100.1 C102.2(N2) C103.2(N2) C104.1 C105.1 C106.1 C107.2(N2) C108.1 C109.2(N2) C110.2(N2) C111.2(N2) C112.2(N2) C113.1 C114.2(N2) C115.1 C116.1 C117.1 C118.1 C121.2(N2) C122.2(N2) C123.2(N2) C124.2(N2) C125.2(N2) C126.2(N2) C127.2(N2) C128.2(N2) C129.1 C130.1 C132.2(N2) C133.2(N2) C134.2(N2) C135.2(N2) C136.2(N2) C137.2(N2) C138.1 C139.2(N2) C140.2(N2) C143.2(N2) C144.2(N2) C145.2(N2) C146.1 C147.2(N2) C148.1 C149.1 C150.1 C151.2(N2) C155.1 C156.2(N2) C157.1 C158.2(N2) C159.2(N2) C160.2(N2) C161.2(N2) C162.2(N2) C163.2(N2) C164.2(N2) C165.2(N2) C166.2(N2) C167.1 C168.1 C169.2(N2) C170.1 C171.2(N2) C172.2(N2) C173.2(N2) C174.2(N2) C175.2(N2) C176.2(N2) C177.2(N2) C179.1 C180.2(N2) C181.1 C182.2(N2) C183.1 C184.2(N2) C185.1 C186.2(N2) C187.2(N2) C188.1 C189.2(N2) C190.1 C191.2(N2) C192.1 C194.2(N2) C195.1 C196.2(N2) C197.1 C198.2(N2) C199.2(N2) C200.2(N2) C201.1 C202.2(N2) C203.2(N2) C204.2(N2) C205.2(N2) C206.2(N2) C207.2(N2) C208.1 C209.1 C210.2(N2) C211.2(N2) C212.2(N2) C213.2(N2) C214.1 C215.1 C217.1 C218.1 C224.1 C225.2(N2) C226.2(N2) C227.2(N2) C228.2(N2) C229.2(N2) C230.2(N2) C231.2(N2) C232.2(N2) C233.2(N2) C234.2(N2) C235.2(N2) C236.1 C237.1 C238.2(N2) C239.2(N2) C240.1 C241.2(N2) C242.1 C243.1 C244.2(N2) C245.2(N2) C246.1 C247.1 C248.1 C249.2(N2) C250.2(N2) C255.2(N2) C256.2(N2) C257.1 C258.1 C259.1 C260.1 C263.2(N2) C264.2(N2) C265.2(N2) C266.2(N2) C267.1 C268.2(N2) C269.2(N2) C270.2(N2) C273.2(N2) C274.2(N2) C275.2(N2) C276.1 C277.2(N2) C278.1 C279.1 C280.1 C281.2(N2) C282.2(N2) C283.2(N2) C284.1 C285.2(N2) C286.1 C287.2(N2) C288.1 C289.2(N2) C290.1 C293.N(N2) C294.2(N2) C295.2(N2) C296.2(N2) C297.2(N2) C298.2(N2) C299.2(N2) C300.2(N2) C301.2(N2) C302.2(N2) C303.2(N2) C304.2(N2) C305.2(N2) C306.2(N2) C307.2(N2) C308.2(N2) C309.2(N2) C310.2(N2) D5.1 D7.1 D9.1 D10.1 D11.1 D12.1 D13.1 D14.1 D15.1 D16.1 D17.1 D18.A(P) D19.1 D20.1 DS1.C E1.2(N2) FL1.B1 FL1.B2 FL1.B3(GND_CH3) FL2.B1 FL2.B2 FL2.B3(GND_CH3) J1.2 J1.3 J1.4 J1.5(SH4) J2.2 J2.3 J2.4 J2.5(SH4) J3.2 J3.3 J3.4 J3.5(SH4) J4.2 J4.3 J4.4 J4.5(SH4) J6.2(SHIELD) L3.2(N2) M1.A1 M1.A12 M1.B1 M1.B12 P1.1 P2.1 P3.1 P4.1 P5.3(N3) P7.3 P9.1 P10.5 P10.6(N6) P11.3 P11.4 P11.9(N9) P11.10 P12.2(N2) P14.3(N3) Q1.S Q2.S Q3.S Q4.S Q9.S Q10.S R11.1 R12.1 R15.1 R16.1 R45.1 R46.1 R49.1 R50.1 R81.1 R83.1 R85.1 R87.1 R91.1 R96.1 R98.1 R99.1 R105.2(N2) R108.1 R110.2(N2) R114.2(N2) R143.1 R148.1 R150.1 R155.1 R167.1 R178.1 R185.1 R187.1 R189.1 R190.1 R198.1 R227.2(N2) R239.2(N2) R241.1 R243.1 R251.2(N2) R254.2(N2) R256.2(N2) R258.2(N2) R259.1 R260.1 R261.1 R262.1 R263.1 R276.1 R278.2(N2) R281.1 R282.1 R285.1 R286.1 R290.1 R292.1 R295.2(N2) R296.1 R302.1 R303.1 R306.1 R307.1 R316.1 R318.1 R323.1 R332.1 R338.1 R342.1 R344.1 R346.1 R348.1 R349.2(N2) R353.1 R362.2(N2) R363.2(N2) R366.2(N2) R367.2(N2) R368.1 R369.1 R370.1 R371.1 S1.2B S2.1 TP13.1(N1) TP36.1(N1) TP37.1(N1) TP38.1(N1) U1.A1 U1.A8 U1.B7 U1.B8 U1.B9 U1.D8 U1.E2 U1.G1 U1.G11 U1.K3 U1.K4 U1.L1 U1.L2 U1.L3 U1.L6 U1.L11 U2.4 U3.3 U6.13 U6.14 U6.15 U6.16 U6.PAD U9.13 U9.14 U9.15 U9.16 U9.PAD U10.13 U10.14 U10.15 U10.16 U10.PAD U11.3 U11.PAD U12.16 U12.PAD U13.5 U13.PAD U14.2 U14.PAD U15.1 U15.15 U15.PAD U16.2 U16.PAD U17.4 U18.3 U18.5 U18.7 U18.8 U18.9 U18.10 U18.31 U18.33 U18.39 U18.40 U18.41 U18.42 U18.44 U18.46 U18.51 U18.54 U18.55 U18.58 U18.62 U19.4 U19.9 U20.6 U21.13 U21.14 U21.15 U21.16 U21.PAD U22.4 U22.PAD U23.2 U24.5 U25.2 U25.3 U25.5 U25.7(VSS) U26.2 U26.PAD U27.4 U27.PAD U28.4 U28.PAD U29.4 U29.PAD U30.1 U30.4 U30.10 U30.11 U30.20 U30.PAD U31.2 U32.3 U33.3 U34.2 U34.3 U34.5 U34.7(VSS) U35.11 U35.PAD U36.10 U37.3 U38.3 U39.5 U40.2 U40.3 U40.12 U41.3 U42.3 U43.2 U43.3 U43.5 U43.7(VSS) U44.2 U44.3 U44.5 U44.7(VSS) Y1.2 Y1.4 Y2.2 Y3.2 Y4.2 Y5.2 Y6.2
P5V_SUPPLY: A5.7 A7.7 A8.7 A14.7 C182.1 C183.2(N2) C187.1 C190.2(N2) C213.1 C215.2(N2) C235.1 C237.2(N2) C239.1 R8.1 R115.1 R228.1 R310.1 U32.2
V1P2_SUPPLY: C18.2(N2) C19.1 C20.2(N2) C21.2(N2) C22.1 C23.2(N2) C24.1 C135.1 C136.1 C138.2(N2) C139.1 C209.2(N2) E6.2(N2) E8.2(N2) E9.2(N2) R225.1 R226.2(N2) TP56.1(N1) U1.B10 U1.C3 U1.E9 U1.F11 U1.H1 U1.J11 U1.L5 U1.L7 U26.5 U26.6
3P3V_SUPPLY: C16.2(N2) C140.1 C143.1 C144.1 C147.1 C148.2(N2) C151.1 C155.2(N2) C162.1 C170.2(N2) C176.1 C194.1 C197.2(N2) C200.1 C201.2(N2) C205.1 C245.1 C246.2(N2) C255.1 C256.1 C257.2(N2) C258.2(N2) C259.2(N2) C267.2(N2) C273.1 C274.1 C275.1 C276.2(N2) C277.1 C281.1 C285.1 C286.2(N2) C288.2(N2) C289.1 C290.2(N2) C294.1 E3.1 E4.2(N2) E7.2(N2) E15.2(N2) E16.1 E17.1 P8.3(N3) P9.5 P9.10 P10.2 P11.1 P11.2 R1.2(N2) R79.2(N2) R89.2(N2) R100.2(N2) R111.2(N2) R149.1 R179.2(N2) R191.2(N2) R192.2(N2) R193.2(N2) R194.2(N2) R196.2(N2) R197.1 R199.2(N2) R200.2(N2) R205.2(N2) R206.2(N2) R207.2(N2) R208.1 R209.1 R210.1 R211.2(N2) R229.2(N2) R230.2(N2) R236.2(N2) R237.1 R238.1 R240.2(N2) R242.2(N2) R244.2(N2) R246.2(N2) R247.2(N2) R250.1 R255.1 R275.2(N2) R279.1 R280.1 R283.1 R284.1 R287.2(N2) R294.2(N2) R313.1 R315.2(N2) R317.2(N2) R320.2(N2) R331.2(N2) R337.2(N2) R352.1 R355.2(N2) R356.1 R357.2(N2) U1.B1 U1.C11 U1.E3 U1.F1 U1.H11 U1.L9 U2.8(VCC) U3.5 U12.2 U16.9 U33.5 U35.4 U36.12(VDD) U37.2(VDD) U38.5 U39.1(VL) U41.5 U42.5 Y4.1 Y4.4(VCC) Y6.4(VDD)
10P5V_SUPPLY: C116.2(N2) D2.C E10.1 R97.2(N2) TP49.1(N1)
4332_A: P11.5 R252.1 U12.20
4332_B: P11.6 R252.2(N2) U12.19
4332_CS: R214.2(N2) R245.1
4332_EN: R246.1 R270.2(N2) R353.2(N2) TP30.1(N1) U12.3
4332_GPIO1: R215.2(N2) U12.11
4332_GPIO2: R216.2(N2) U12.12
4332_GPIO3: R217.2(N2) U12.13
4332_INT: R248.1 U12.10
4332_Y: P11.8 R250.2(N2) U12.17
4332_Z: P11.7 R251.1 U12.18(Z)
7768_VCM: R117.1 U18.59
-10P5_SUPPLY: C117.2(N2) D3.A(P) E11.1 R95.2(N2) TP50.1(N1)
AC_WAVE_SIGNAL: A7.6 C292.2(N2) R156.2(N2) TP31.1(N1) U20.4(VREF)
AD5543_CS: R133.1 U20.8
AD5686_GAIN: R137.1 U16.8
AD5686_LDAC: R166.1 U16.7
AD5686_RSTSEL: R144.1 U16.14
AD5686R_RST: R146.1 U16.13
AD5686R_SYNC: R136.1 R355.1 U16.11
AD7768_CS: R134.1 R356.2(N2) U18.16
AD7768_DCLK: R140.1 TP40.1(N1) U18.28
AD7768_DRDY: R141.1 TP39.1(N1) U18.29
AD7768_FILTER: R259.2(N2) U18.11
AD7768_FORMAT0: R257.2(N2) U18.56
AD7768_MODE0: R263.2(N2) U18.12
AD7768_MODE1: R262.2(N2) U18.13
AD7768_MODE2: R261.2(N2) U18.14
AD7768_MODE3: R260.2(N2) U18.15
AD7768_RST: R147.1 U18.30
AD7768_START: R152.1 U18.37
AD9833_FSYNC: R130.1 U19.8
ADC_REF: C157.2(N2) R88.2(N2) R138.2(N2) R139.2(N2) U18.6 U18.43 VREF.1(N1)
ADP5071_EN: R89.1 R98.2(N2) R126.1 U15.9 U15.11
ADP7142_ADJ: R80.1 R81.2(N2) R277.1 U11.2
BNC_CTRL: R273.2(N2) U32.8
CH0_COUP_OPT: R218.2(N2) U22.6 U22.15
CH0_COUPLED: C119.1 R53.1 U22.9 U22.16
CH0_G0: A10.5 U40.4
CH0_G1: A10.6 U40.5
CH0_G2: A10.7 U40.6
CH0_OUT_N: C83.2(N2) C85.2(N2) R73.2(N2) TP14.1(N1) U18.63
CH0_OUT_P: C83.1 C86.2(N2) R74.2(N2) TP15.1(N1) U18.64
CH0_SHIFT: A3.3 C6.2(N2) C263.1 R2.2(N2)
CH0_VOCM: A17.1(VOUT) A17.4 R59.1 R298.2(N2) U9.9(VOCM)
CH1_COUP_OPT: R272.2(N2) U27.6 U27.15
CH1_COUPLED: C120.1 R54.1 U27.9 U27.16
CH1_G0: A11.5 U40.7
CH1_G1: A11.6 U40.8
CH1_G2: A11.7 U40.9
CH1_OUT_N: C84.2(N2) C87.2(N2) R75.2(N2) TP16.1(N1) U18.1
CH1_OUT_P: C84.1 C88.2(N2) R76.2(N2) TP17.1(N1) U18.2
CH1_SHIFT: A4.3 C11.2(N2) C264.1 R5.2(N2)
CH1_VOCM: A16.1(VOUT) A16.4 R60.1 R299.2(N2) U10.9(VOCM)
CH2_COUP_OPT: R232.2(N2) U28.6 U28.15
CH2_COUPLED: C131.1 R19.1 U28.9 U28.16
CH2_G0: A12.5 U40.10
CH2_G1: A12.6 U40.11
CH2_G2: A12.7 U40.13
CH2_OUT_N: C51.2(N2) C53.2(N2) R39.2(N2) TP6.1(N1) U18.50
CH2_OUT_P: C51.1 C54.1 R40.2(N2) TP8.1(N1) U18.49
CH2_SHIFT: A1.3 C7.2(N2) C265.1 R3.2(N2)
CH2_VOCM: A18.1(VOUT) A18.4 R25.1 R300.2(N2) U21.9(VOCM)
CH3_COUP_OPT: R233.2(N2) U29.6 U29.15
CH3_COUPLED: C153.1 R20.1 U29.9 U29.16
CH3_G0: A13.5 U40.14
CH3_G1: A13.6 U40.15
CH3_G2: A13.7 U40.16
CH3_OUT_N: C52.2(N2) C55.2(N2) R41.2(N2) TP9.1(N1) U18.48
CH3_OUT_P: C52.1 C56.2(N2) R42.2(N2) TP10.1(N1) U18.47
CH3_SHIFT: A2.3 C10.2(N2) C266.1 R4.2(N2)
CH3_VOCM: A19.1(VOUT) A19.4 R26.1 R301.2(N2) U6.9(VOCM)
CH_FDA_DIS: R127.1 U6.12 U9.12 U10.12 U21.12
CH_FDA_MODE: R129.1 U6.5 U9.5 U10.5 U21.5
CLKIN_32: R183.2(N2) U1.D6
CON_CC1: D15.2(N2) M1.A5 TP63.1(N1) U36.1
CON_CC2: D14.2(N2) M1.B5 TP62.1(N1) U36.2
CON_DN: FL1.A2 M1.A7 M1.B7
CON_DP: FL1.A1 M1.A6 M1.B6
CON_RX1_N: FL1.A5 M1.B10
CON_RX1_P: FL1.A6 M1.B11
CON_RX2_N: FL2.A4 M1.A10
CON_RX2_P: FL2.A3 M1.A11
CON_TX1_N: FL1.A3 M1.A3
CON_TX1_P: FL1.A4 M1.A2
CON_TX2_N: FL2.A6 M1.B3
CON_TX2_P: FL2.A5 M1.B2
CON_VBUS: D12.2(N2) E5.1 M1.A4 M1.A9 M1.B4(VBUS_4) M1.B9
CVDDQ: C150.2(N2) C161.1 C203.1 E7.1 R180.1 R184.2(N2) R186.2(N2) R188.2(N2) U1.B6 Y2.4(VCC)
DAC_OUTA: C4.2(N2) R2.1 U16.1
DAC_OUTB: C9.2(N2) R5.1 U16.16
DAC_OUTC: C5.2(N2) R3.1 U16.4
DAC_OUTD: C8.2(N2) R4.1 U16.5
DOUT_CH0: R118.1 TP41.1(N1) U18.27
DOUT_CH1: R119.1 TP42.1(N1) U18.26
DOUT_CH2: R120.1 TP43.1(N1) U18.25
DOUT_CH3: R268.1 TP44.1(N1) U18.24
EN_LOAD_RES: Q9.G R163.1 R342.2(N2) TP20.1(N1)
EN_OTG: R350.1 R354.2(N2) U42.4(Y)
EXT_BUSY: P9.3 R213.2(N2)
EXT_I2C_CS: P10.1 R236.1
EXT_I2C_SCLK: P10.4 R234.2(N2) R238.2(N2) TP33.1(N1) U36.8 U39.2
EXT_I2C_SDA: P10.3 R235.2(N2) R237.2(N2) TP35.1(N1) U36.7 U39.3
EXT_SPI_CS: P9.6 R223.2(N2) R357.1
EXT_SPI_INT1: P9.4 R161.2(N2)
EXT_SPI_INT2: P9.2 R212.2(N2)
FSLC0: R184.1 R185.2(N2) U1.B2
FSLC1: R186.1 R187.2(N2) U1.B4
FSLC2: R188.1 R189.2(N2) U1.E6
IEPE_CH0: R47.2(N2) R49.2(N2) U22.1
IEPE_CH1: R48.2(N2) R50.2(N2) U27.1
IEPE_CH2: R13.2(N2) R15.2(N2) U28.1
IEPE_CH3: R14.2(N2) R16.2(N2) U29.1
INT_N_CTL15: R179.1 U1.L8
LED_GPIO4: R165.1 R181.1 TP23.1(N1)
LOW_SIDE_CH0: D7.2(N2) J1.1 P1.2(N2) R45.2(N2) R47.1 U25.8
LOW_SIDE_CH1: D9.2(N2) J2.1 P2.2(N2) R46.2(N2) R48.1 U34.8
LOW_SIDE_CH2: D10.2(N2) J3.1 P3.2(N2) R11.2(N2) R13.1 U43.8
LOW_SIDE_CH3: D11.2(N2) J4.1 P4.2(N2) R12.2(N2) R14.1 R341.2(N2) U44.8
LT3092_SIDE_CH0: C59.1 C63.1 R43.1 R51.1 U25.1
LT3092_SIDE_CH1: C60.1 C64.1 R44.1 R52.1 U34.1
LT3092_SIDE_CH2: C27.1 C31.1 R9.1 R17.1 U43.1
LT3092_SIDE_CH3: C28.1 C32.1 R10.1 R18.1 U44.1
LT3092_SW_CH0: R271.2(N2) R368.2(N2) U25.6
LT3092_SW_CH1: R220.2(N2) R369.2(N2) U34.6
LT3092_SW_CH2: R221.2(N2) R370.2(N2) U43.6
LT3092_SW_CH3: R222.2(N2) R371.2(N2) U44.6
LTC3112_FB: C222.1 R288.1 R289.1 R290.2(N2) R291.2(N2) U30.3
LTC3112_RUN: R171.2(N2) R287.1 U30.7
MB_CLOCK_IN: R164.1 R339.1 R340.1 TP22.1(N1)
MB_CLOCK_OUT: D20.2(N2) P14.2 R334.2(N2) R335.2(N2)
MB_HOST: R172.2(N2) R313.2(N2) U3.2
MB_MODE: R162.1 R330.1 TP19.1(N1) U37.1
MB_OSC_IN: U37.6 Y6.3
MB_SLAVE: R173.2(N2) U33.4(Y)
MCLK: R373.2(N2) R375.2(N2) U18.32(XTAL2/MCLK)
MCLK_SEL: R219.2(N2) R372.1
MDAC_SIGNAL: A8.6 C193.1 R159.1 TP58.1(N1) U20.3 U32.7
N5V_SUPPLY: A5.4(V-) A7.4(V-) A8.4(V-) A14.4(V-) C14.1 C15.2(N2) C186.1 C188.2(N2) C189.1 C214.2(N2) C234.1 C236.2(N2) C238.1 R116.1 R121.1 R311.2(N2) R360.1 R361.1 R364.1 R365.1 U32.4(VSS)
N_SRST: P7.10 R196.1
OTG_ID: R79.1 R350.2(N2) TP66.1(N1) U1.C9 U36.9 U42.1
PGA_SCLK: R322.2(N2) U39.7 U40.22
PGA_SDA: R321.2(N2) U39.6 U40.23
PMODE0: R168.2(N2) R192.1
PMODE1: R169.2(N2) S1.1A
PMODE2: R170.2(N2) S1.2A
PORT_SEL: R1.1 R114.1 U35.12 U36.11
REF_BUF_EN: A6.5 A9.5 R269.1
RESERVED1: R122.1 TP27.1(N1)
RESERVED2: R123.1 TP67.1(N1)
RESERVED3: R124.1 TP68.1(N1)
RESERVED4: R125.1 TP69.1(N1)
RESERVED5: R145.1 TP71.1(N1)
RTCK: P7.7 R205.1
RX1_N: FL1.C5 U35.16
RX1_P: FL1.C6 U35.15
RX2_N: FL2.C4 U35.1
RX2_P: FL2.C3 U35.2
RXVDDQ: C195.2(N2) C198.1 E8.1 U1.A2
SPI_CLK: P9.9(N9) R174.2(N2) R203.1 TP34.1(N1) U12.7 U16.10 U18.17 U19.7 U20.1
SPI_CLK_FLASH: R203.2(N2) R211.1 U2.6
SPI_MISO: P9.8 R176.2(N2) R202.1 TP26.1(N1) U12.9 U16.6 U18.19
SPI_MISO_FLASH: R197.2(N2) R202.2(N2) U2.2
SPI_MOSI: P9.7 R177.2(N2) R201.1 TP28.1(N1) U12.8 U16.12 U18.18 U19.6 U20.2
SPI_MOSI_FLASH: R201.2(N2) R210.2(N2) U2.5
SPI_RESET_FLASH: R209.2(N2) U2.7
SPI_SSN: R175.2(N2) R204.1
SPI_SSN_FLASH: R193.1 R204.2(N2) U2.1
SPI_WP_FLASH: R194.1 R198.2(N2) U2.3
SS_DM: FL1.C2 U1.A10
SS_DP: FL1.C1 U1.A9
SS_RX_M: C272.1 U35.14
SS_RX_P: C271.1 U35.13
SS_TX_M: C141.2(N2) U35.9
SS_TX_P: C142.2(N2) U35.10
SYNC_IN: R151.1 U18.36
SYS_HWRST: C206.1 D17.2(N2) R208.2(N2) S2.2(B) U1.C5
SYS_POWER: C93.1 C97.1 C103.1 C104.2(N2) C217.2(N2) C280.2(N2) E13.2(N2) L1.2(N2) R102.1 R274.2(N2) TP48.1(N1) U13.6(VIN) U13.8 U14.3 U14.4 U15.17 U15.18 U15.19 U30.5 U30.6
TCK: P7.4 R207.1 U1.F6
TDI: P7.8 R200.1 U1.E7
TDO: P7.6 R206.1 U1.C10
TMS: P7.2 R229.1 U1.E8
TRIGGER: D8.A(P) D13.2(N2) P5.1 P14.1 R314.2(N2) R315.1 R333.2(N2)
TRST_N: P7.9(N9) R199.1 U1.B11
TX1_N: C253.2(N2) U35.6
TX1_P: C251.2(N2) U35.5
TX2_N: C254.2(N2) U35.7
TX2_P: C252.2(N2) U35.8
TXVDDQ: C149.2(N2) C156.1 E6.1 U1.B5
UNNAMED_22_ADP5071V2_I1_COMP1: C109.1 R92.1 U15.8
UNNAMED_22_ADP5071V2_I1_COMP2: C110.1 R94.1 U15.12
UNNAMED_22_ADP5071V2_I1_FB1: R96.2(N2) R97.1 U15.7
UNNAMED_22_ADP5071V2_I1_FB2: R93.2(N2) R95.1 U15.13
UNNAMED_22_ADP5071V2_I1_INBK: L2.2(N2) U15.3
UNNAMED_22_ADP5071V2_I1_SEQ: R82.1 R83.2(N2) U15.5
UNNAMED_22_ADP5071V2_I1_SLEW: R84.1 R85.2(N2) U15.6
UNNAMED_22_ADP5071V2_I1_SS: R276.2(N2) U15.10
UNNAMED_22_ADP5071V2_I1_SW1: D2.A(P) L2.1 U15.2
UNNAMED_22_ADP5071V2_I1_SW2: D3.C L3.1 U15.20
UNNAMED_22_ADP5071V2_I1_SYNC: R86.1 R87.2(N2) U15.4
UNNAMED_22_ADP5071V2_I1_VREF: C113.2(N2) R93.1 U15.14
UNNAMED_22_ADP7118V2_I56_EN: R103.1 U23.3
UNNAMED_22_ADP7118V2_I56_SENSE: R109.1 R110.1 U23.4
UNNAMED_22_ADP7118V2_I56_VIN: C123.1 C125.1 E10.2(N2) R103.2(N2) U23.1
UNNAMED_22_ADP7118V2_I56_VOUT: C128.1 R109.2(N2) R115.2(N2) TP52.1(N1) U23.5(VOUT)
UNNAMED_22_ADP7182V5_I66_ADJ: R105.1 R106.1 U24.2
UNNAMED_22_ADP7182V5_I66_EN: R104.1 U24.3
UNNAMED_22_ADP7182V5_I66_EPAD: C122.1 C124.1 E11.2(N2) R104.2(N2) U24.6 U24.PAD
UNNAMED_22_ADP7182V5_I66_VOUT: C126.1 R106.2(N2) R116.2(N2) TP53.1(N1) U24.1(VOUT)
UNNAMED_22_CAP_I38_N1: C112.1 R94.2(N2)
UNNAMED_22_CAP_I280_N1: C111.1 R92.2(N2)
UNNAMED_22_CAP_I337_N1: C1.1 E1.1 M1.SH1 M1.SH2 M1.SH3 M1.SH4
UNNAMED_22_CAP_I400_N1: C253.1 FL1.C3
UNNAMED_22_CAP_I401_N1: C251.1 FL1.C4
UNNAMED_22_CAP_I402_N1: C252.1 FL2.C5
UNNAMED_22_CAP_I403_N1: C254.1 FL2.C6
UNNAMED_22_ICCBTU02043_I388_XSD: R296.2(N2) U35.3(XSD)
UNNAMED_22_ICPTN5150A_I359_ADR: R316.2(N2) U36.5
UNNAMED_22_ICPTN5150A_I359_INTB: R317.1 U36.6
UNNAMED_22_ICPTN5150A_I359_PORT: R100.1 R292.2(N2) U36.3
UNNAMED_22_ICPTN5150A_I359_VBUSDET: R101.1 U36.4
UNNAMED_23_74125V5_I307_A: R349.1 U42.2
UNNAMED_23_ADLT8330_I322_FBX: C311.2(N2) R90.1 R91.2(N2) U13.1
UNNAMED_23_ADLTC3112_I90_IOUT: R295.1 U30.8
UNNAMED_23_ADLTC3112_I90_PWM: R294.1 U30.19
UNNAMED_23_ADP1708_I291_ADJ: R107.1 R108.2(N2) U14.8
UNNAMED_23_ADP1708_I291_EN: R102.2(N2) U14.1
UNNAMED_23_ADP1708_I291_OUT: C94.1 E15.1 R107.2(N2) R113.1 TP51.1(N1) U14.5 U14.6
UNNAMED_23_ADP1708_I291_SENSE: R113.2(N2) U14.7(SENSE)
UNNAMED_23_ADP7118V2_I83_EN: C225.1 E14.2(N2) U31.1 U31.3
UNNAMED_23_ADP7118V2_I83_SENSE: R158.2(N2) R278.1 U31.4
UNNAMED_23_ADP7118V2_I83_VOUT: C227.1 R158.1 R293.2(N2) TP55.1(N1) U31.5(VOUT)
UNNAMED_23_ADP7142_I123_EN: C89.1 C91.1 E12.2(N2) U11.4 U11.6
UNNAMED_23_ADP7142_I123_SS: C92.2(N2) U11.5
UNNAMED_23_CAP_I54_N1: C219.1 L4.2(N2) U30.15 U30.16
UNNAMED_23_CAP_I54_N2: C219.2(N2) U30.17
UNNAMED_23_CAP_I55_N1: C220.1 L4.1 U30.12 U30.13
UNNAMED_23_CAP_I55_N2: C220.2(N2) U30.14
UNNAMED_23_CAP_I58_N2: C218.2(N2) U30.18
UNNAMED_23_CAP_I63_N2: C223.2(N2) C224.2(N2) E14.1 R289.2(N2) TP54.1(N1) U30.9(VOUT)
UNNAMED_23_CAP_I65_N1: C221.1 C222.2(N2) U30.2
UNNAMED_23_CAP_I65_N2: C221.2(N2) R288.2(N2)
UNNAMED_23_CAP_I72_N1: C223.1 R291.1
UNNAMED_23_CAP_I109_N1: C95.1 R277.2(N2)
UNNAMED_23_CAP_I117_N2: C100.2(N2) U13.7
UNNAMED_23_CAP_I241_N2: C247.2(N2) C248.2(N2) D18.C F1.2(N2) Q6.3 R325.1 R347.2(N2) TP70.1(N1)
UNNAMED_23_CAP_I249_N2: C279.2(N2) C284.2(N2) C293.P E13.1 Q7.3 Q8.3 R336.2(N2)
UNNAMED_23_CAP_I257_N1: C261.1 Q5.2(S) Q7.2(S) R328.1
UNNAMED_23_CAP_I257_N2: C261.2(N2) Q5.1 Q7.1 R326.1 R328.2(N2) R354.1
UNNAMED_23_CAP_I260_N1: C262.1 Q6.2(S) Q8.2(S) R329.1
UNNAMED_23_CAP_I260_N2: C262.2(N2) Q6.1 Q8.1 R327.1 R329.2(N2)
UNNAMED_23_CAP_I272_N2: C260.2(N2) Q4.G R325.2(N2) R348.2(N2)
UNNAMED_23_CAP_I299_N1: C287.1 R336.1
UNNAMED_23_CN2P_I240_N1: D16.2(N2) F1.1 P12.1
UNNAMED_23_DIOLED_I278_P: DS1.A(P) R111.1
UNNAMED_23_DIOSCHOTTKY_I115_P: D1.A(P) L1.1 U13.3 U13.4
UNNAMED_23_RES_I270_N2: Q1.D Q3.G R297.2(N2)
UNNAMED_23_RES_I295_N2: Q4.D R327.2(N2)
UNNAMED_23_RES_I296_N2: Q3.D R326.2(N2)
UNNAMED_23_RES_I302_N1: Q1.G R346.2(N2) R347.1
UNNAMED_24_ADA49451_I49_: C76.2(N2) R70.2(N2) U9.4
UNNAMED_24_ADA49451_I49__1: C76.1 R66.2(N2) U9.3
UNNAMED_24_ADA49451_I49__2: C75.1 R65.2(N2) U9.2
UNNAMED_24_ADA49451_I49__3: C75.2(N2) R69.2(N2) U9.1
UNNAMED_24_ADA49451_I49__4: R74.1 U9.10
UNNAMED_24_ADA49451_I49__5: R73.1 U9.11
UNNAMED_24_ADA49451_I63_: C77.1 R67.2(N2) U10.2
UNNAMED_24_ADA49451_I63__1: C78.1 R68.2(N2) U10.3
UNNAMED_24_ADA49451_I63__2: C77.2(N2) R71.2(N2) U10.1
UNNAMED_24_ADA49451_I63__3: C78.2(N2) R72.2(N2) U10.4
UNNAMED_24_ADA49451_I63__4: R76.1 U10.10
UNNAMED_24_ADA49451_I63__5: R75.1 U10.11
UNNAMED_24_ADLTC6910X_I158_AGND: A10.2 C226.1 R298.1 R302.2(N2) R304.1
UNNAMED_24_ADLTC6910X_I158_IN: A3.1(VOUT) A10.3 C65.2(N2) R55.2(N2)
UNNAMED_24_ADLTC6910X_I158_OUT: A10.1 R57.1 TP11.1(N1)
UNNAMED_24_ADLTC6910X_I163_AGND: A11.2 C228.1 R299.1 R303.2(N2) R305.1
UNNAMED_24_ADLTC6910X_I163_IN: A4.1(VOUT) A11.3 C66.2(N2) R56.2(N2)
UNNAMED_24_ADLTC6910X_I163_OUT: A11.1 R58.1 TP12.1(N1)
UNNAMED_24_CAP_I12_N2: C61.2(N2) R51.2(N2) U7.2 U7.3 U7.4
UNNAMED_24_CAP_I13_N2: C59.2(N2) R43.2(N2) U7.5(SET)
UNNAMED_24_CAP_I35_N1: A3.4 C65.1 R53.2(N2) R55.1
UNNAMED_24_CAP_I37_N1: C71.1 R57.2(N2) R62.1
UNNAMED_24_CAP_I37_N2: C71.2(N2) R59.2(N2) R61.1
UNNAMED_24_CAP_I42_N1: C73.1 R62.2(N2) R66.1 R70.1
UNNAMED_24_CAP_I42_N2: C73.2(N2) R61.2(N2) R65.1 R69.1
UNNAMED_24_CAP_I67_N1: C74.1 R64.2(N2) R68.1 R72.1
UNNAMED_24_CAP_I67_N2: C74.2(N2) R63.2(N2) R67.1 R71.1
UNNAMED_24_CAP_I71_N1: C72.1 R58.2(N2) R64.1
UNNAMED_24_CAP_I71_N2: C72.2(N2) R60.2(N2) R63.1
UNNAMED_24_CAP_I80_N2: C62.2(N2) R52.2(N2) U8.2 U8.3 U8.4
UNNAMED_24_CAP_I83_N2: C60.2(N2) R44.2(N2) U8.5(SET)
UNNAMED_24_CAP_I86_N1: A4.4 C66.1 R54.2(N2) R56.1
UNNAMED_24_RES_I182_N2: A17.3 C307.1 R7.2(N2) R78.2(N2)
UNNAMED_24_RES_I184_N2: A16.3 C308.1 R264.2(N2) R265.2(N2)
UNNAMED_25_ADA49451_I78_: C43.2(N2) R35.2(N2) U21.1
UNNAMED_25_ADA49451_I78__1: C44.2(N2) R36.2(N2) U21.4
UNNAMED_25_ADA49451_I78__2: C43.1 R31.2(N2) U21.2
UNNAMED_25_ADA49451_I78__3: C44.1 R32.2(N2) U21.3
UNNAMED_25_ADA49451_I78__4: R40.1 U21.10
UNNAMED_25_ADA49451_I78__5: R39.1 U21.11
UNNAMED_25_ADA49451_I92_: C45.1 R33.2(N2) U6.2
UNNAMED_25_ADA49451_I92__1: C46.1 R34.2(N2) U6.3
UNNAMED_25_ADA49451_I92__2: C45.2(N2) R37.2(N2) U6.1
UNNAMED_25_ADA49451_I92__3: C46.2(N2) R38.2(N2) U6.4
UNNAMED_25_ADA49451_I92__4: R42.1 U6.10
UNNAMED_25_ADA49451_I92__5: R41.1 U6.11
UNNAMED_25_ADLTC6910X_I163_AGND: A12.2 C231.1 R300.1 R307.2(N2) R309.1
UNNAMED_25_ADLTC6910X_I163_IN: A1.1(VOUT) A12.3 C33.2(N2) R21.2(N2)
UNNAMED_25_ADLTC6910X_I163_OUT: A12.1 R23.1 TP5.1(N1)
UNNAMED_25_ADLTC6910X_I168_AGND: A13.2 C232.1 R301.1 R306.2(N2) R308.1
UNNAMED_25_ADLTC6910X_I168_IN: A2.1(VOUT) A13.3 C34.2(N2) R22.2(N2)
UNNAMED_25_ADLTC6910X_I168_OUT: A13.1 R24.1 TP4.1(N1)
UNNAMED_25_CAP_I24_N2: C30.2(N2) R18.2(N2) U5.2 U5.3 U5.4
UNNAMED_25_CAP_I38_N1: A1.4 C33.1 R19.2(N2) R21.1
UNNAMED_25_CAP_I41_N2: C27.2(N2) R9.2(N2) U4.5(SET)
UNNAMED_25_CAP_I44_N2: C29.2(N2) R17.2(N2) U4.2 U4.3 U4.4
UNNAMED_25_CAP_I53_N1: C40.1 R24.2(N2) R30.1
UNNAMED_25_CAP_I53_N2: C40.2(N2) R26.2(N2) R29.1
UNNAMED_25_CAP_I56_N1: C42.1 R30.2(N2) R34.1 R38.1
UNNAMED_25_CAP_I56_N2: C42.2(N2) R29.2(N2) R33.1 R37.1
UNNAMED_25_CAP_I70_N1: C39.1 R23.2(N2) R28.1
UNNAMED_25_CAP_I70_N2: C39.2(N2) R25.2(N2) R27.1
UNNAMED_25_CAP_I74_N1: C41.1 R28.2(N2) R32.1 R36.1
UNNAMED_25_CAP_I74_N2: C41.2(N2) R27.2(N2) R31.1 R35.1
UNNAMED_25_CAP_I94_N2: C28.2(N2) R10.2(N2) U5.5(SET)
UNNAMED_25_RES_I15_N2: A2.4 C34.1 R20.2(N2) R22.1
UNNAMED_25_RES_I181_N1: Q9.D R341.1
UNNAMED_25_RES_I185_N2: A18.3 C310.1 R358.2(N2) R359.2(N2)
UNNAMED_25_RES_I187_N2: A19.3 C309.1 R266.2(N2) R267.2(N2)
UNNAMED_26_ADG5436_I1_EN: R279.2(N2) U22.12
UNNAMED_26_ADG5436_I1_S1B: C119.2(N2) U22.2
UNNAMED_26_ADG5436_I1_S2B: R281.2(N2) U22.10
UNNAMED_26_ADG5436_I1_VSS: R360.2(N2) R362.1 U22.3(VSS)
UNNAMED_26_ADG5436_I17_EN: R280.2(N2) U27.12
UNNAMED_26_ADG5436_I17_S1B: C120.2(N2) U27.2
UNNAMED_26_ADG5436_I17_S2B: R282.2(N2) U27.10
UNNAMED_26_ADG5436_I17_VSS: R361.2(N2) R363.1 U27.3(VSS)
UNNAMED_26_ADG5436_I20_EN: R283.2(N2) U28.12
UNNAMED_26_ADG5436_I20_S1B: C131.2(N2) U28.2
UNNAMED_26_ADG5436_I20_S2B: R285.2(N2) U28.10
UNNAMED_26_ADG5436_I20_VSS: R364.2(N2) R366.1 U28.3(VSS)
UNNAMED_26_ADG5436_I29_EN: R284.2(N2) U29.12
UNNAMED_26_ADG5436_I29_S1B: C153.2(N2) U29.2
UNNAMED_26_ADG5436_I29_S2B: R286.2(N2) U29.10
UNNAMED_26_ADG5436_I29_VSS: R365.2(N2) R367.1 U29.3(VSS)
UNNAMED_27_AD55X3_I1_IOUT: A8.2 C193.2(N2) U20.5
UNNAMED_27_AD9833_I8_CAP: C180.1 C181.2(N2) CAP2.5.1(N1) U19.3
UNNAMED_27_AD9833_I8_COMP: C178.1 U19.1
UNNAMED_27_AD9833_I8_MCLK: R153.1 U19.5
UNNAMED_27_AD9833_I8_VOUT: R154.1 R343.1 U19.10(VOUT)
UNNAMED_27_ADA45221_I217_: A7.2 C291.1 C292.1 R155.2(N2) R156.1
UNNAMED_27_ADA45221_I217__1: A7.3 R154.2(N2) R157.2(N2) R344.2(N2) TP29.1(N1)
